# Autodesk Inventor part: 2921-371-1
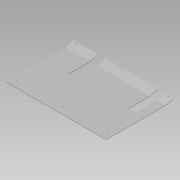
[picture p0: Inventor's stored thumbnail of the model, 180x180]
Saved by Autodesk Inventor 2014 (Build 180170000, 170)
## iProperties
Company: NHTSA/VRTC
Created: 2012-12
Part Number: 2921-371-1
Project: CHILD SIDE IMPACT SLED
Material: Steel, Mild
Description: SEAT BOTTOM CUSHION MTG. PLATE
Document SubType Name: Modeling
Designer: Mike Vanvoorhis
Mass: 4029.92 g
Surface Area: 5188.18 cm^2
Volume: 512.713 cm^3
Density: 7.86 g/cm^3
Appearance: Steel
Stock Number: PL 14 Ga. x 635.0 (25") x 431.0 (16 15/16")
DESIGN DATE: 2012-11-05
Title: Seat Bottom Cushion Mtg. Plate
Subject: Child Side Impact Sled
Author: Dave Walker
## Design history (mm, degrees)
sketch "Sketch1"
  geometry: L1 (-376.263, 2)-(-0.263, 2); L2 (0, 0)-(-376.263, 0); L3 (-376.263, 0)-(-376.263, 2); L4 (-0.263, 2)-(52.863, 16.235); L5 (52.863, 16.235)-(53.38, 14.303); L6 (53.38, 14.303)-(0, 0); L7 (0, 19.482)-(0, -3.247) reference; L8 (-462.192, 0)-(139.309, 0) reference
  constraints: 12 end point, 2 parallel, 2 perpendicular, 1 collinear, 1 horizontal, 1 point on line
  dimensions: "d0" = 2 distance of L2.end L1.start; "d1" = 2 distance between parallel lines of L6 L4 (= d0); "d2" = 376 distance from line of L1.end L3; "d3" = 55 distance from line of L1.end L5; "d4" = 15 deg angle of L6 L2
extrude "Extrusion1" new body sketch "Sketch1" stored distance "d5" = 635; taper "d6" = 0 deg
sketch "Sketch2"
  geometry: L1 (376, 0)-(376, -635) reference; L2 (429.644, -55)-(240.5, -55); L3 (240.5, -55)-(240.5, -100); L4 (240.5, -100)-(429.644, -100); L5 (429.644, -100)-(429.644, -55); L6 (429.644, -435)-(240.5, -435); L7 (240.5, -435)-(240.5, -480); L8 (240.5, -480)-(429.644, -480); L9 (429.644, -480)-(429.644, -435); L10 (429.644, 0)-(429.644, -635) reference; L11 (429.644, 0)-(376.263, 0) reference; L12 (376.263, -635)-(429.644, -635) reference; 1 further point
  constraints: 16 end point, 4 parallel, 3 collinear, 2 horizontal, 2 perpendicular
  dimensions: "d7" = 135.5 distance between parallel lines of L3 L1; "d8" = 55 distance between parallel lines of L2 L11; "d9" = 45 distance between parallel lines of L4 L2; "d11" = 45 distance between parallel lines of L6 L8 (= d9); "d24" = 380 distance between parallel lines of L6 L2
extrude "Extrusion2" cut sketch "Sketch2" stored distance "d12" = 800; taper "d13" = 0 deg
sketch "Sketch3"
  geometry: L1 (0, -635)-(376, -635) reference; L2 (0, 0)-(0, -635) reference; 4 further points
  constraints: 2 vertical alignment
  dimensions: "d14" = 25 distance from line of point (40, -610) L1; "d15" = 317.5 distance from line of point (40, -317.5) L1; "d16" = 610 distance from line of point (40, -25) L1; "d25" = 40 distance from line of point (40, -610) L2
hole "Hole1" sketch "Sketch3" at (40, -610), (40, -317.5), (40, -25) diameter "d17" = 7.14375; stored, may be unused: countersink angle "d21" = 90 deg, drill point angle "d23" = 118 deg; dims "d18" = 6, "d19" = 4, "d20" = 2, "d22" = 8
sketch "Sketch4"
  geometry: L1 (0, 0)-(0, 335) reference; 7 further points; 3 other entities
  constraints: 3 horizontal alignment, 2 vertical alignment, 3 other
  dimensions: "d28" = 10 distance from line of point (-10, 510) L1
hole "Hole2" sketch "Sketch4" at (-10, 510), (-10, 217.5), (-10, -75) diameter "d29" = 7.14375; stored, may be unused: countersink angle "d33" = 90 deg, drill point angle "d35" = 118 deg; dims "d30" = 6, "d31" = 4, "d32" = 2, "d34" = 8
body "Solid1"
